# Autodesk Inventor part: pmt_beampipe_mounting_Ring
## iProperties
Shininess: 64.0
Length Units: 11269
Angle Units: 11279
Time Units: 11290
Mass Units: 11283
Length Display Precision: 3
Angle Display Precision: 2
Compacted: True
Part Number: pmt_beampipe_mounting_Ring
Document SubType Name: Modeling
Created: 2004-08
Designer: John Blackburn
Manufacturer: Standard
Standards Organization: Custom
Material: Aluminum-6061
Density: 0.0
Volumn: 0.0
Area: 0.0
PropertySet Name: Model Information
Control State: 0
Master: False
Checked Out: False
Author: John Blackburn
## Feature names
1. Extrusion1
2. Extrusion3
3. Hole1
4. Extrusion4
5. Hole2
6. Extrusion5
7. Split1
